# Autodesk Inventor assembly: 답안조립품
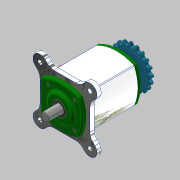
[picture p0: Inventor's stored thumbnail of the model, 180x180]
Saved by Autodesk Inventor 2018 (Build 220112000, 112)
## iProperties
Created: 2022-01
Part Number: 답안조립품
Material: 일반
Document SubType Name: Assembly
Designer: home
Author: home
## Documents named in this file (13)
- C:\Users\home\Desktop\720106V1027\답안조립품.iam
- C:\Users\home\Desktop\720106V1027\본체.ipt
- C:\Users\home\Desktop\720106V1027\커버.ipt
- C:\Users\home\Desktop\720106V1027\베어링 6203.ipt
- C:\Users\home\Desktop\720106V1027\편심축.ipt
- C:\Users\home\Desktop\720106V1027\오일 실 17 x 30 x 8.ipt
- C:\Users\home\Desktop\720106V1027\키 5 x 5.ipt
- C:\Users\home\Desktop\720106V1027\스프로킷.ipt
- C:\Users\home\Desktop\720106V1027\부시.ipt
- C:\Users\home\Desktop\720106V1027\슬라이더.ipt
- C:\Users\home\Desktop\720106V1027\와셔 4 x 20.ipt
- C:\Users\home\Desktop\720106V1027\육각머리볼트 M4.ipt
- C:\Users\home\Desktop\720106V1027\볼트 M4 x 12.ipt
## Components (8 placed, 1 different names)
1. M4x0.7x12:1
2. M4x0.7x12:3
3. M4x0.7x12:4
4. M4x0.7x12:5
5. M4x0.7x12:2
6. M4x0.7x12:6
7. M4x0.7x12:7
8. M4x0.7x12:8
